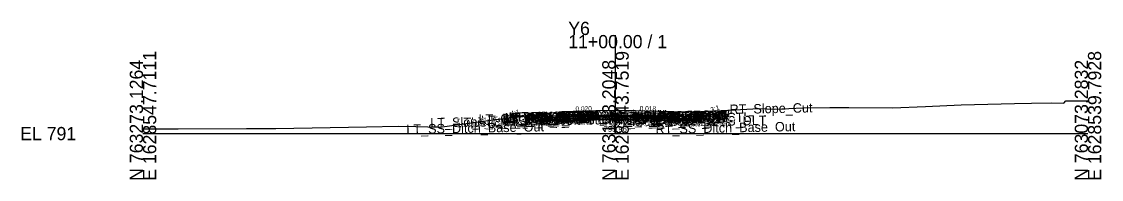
# Model space of a CAD drawing. Extents: x -26 to 203, y -10 to 6017.
# Drawn here: x -25.7 to 202.8, y 1990.3 to 2023.7 of the extents above; entities that cross this region are included whole.
import ezdxf

# ---------------------------------------------------------------- set-up
doc = ezdxf.new("R2010")
doc.units = 0
for name, color, linetype in [('Default', 7, 'Continuous'), ('Exist Cross Section Cell', 7, 'Continuous'), ('Exist XS Center Line Elevation Label', 7, 'Continuous'), ('Exist XS Ground Line', 7, 'Continuous'), ('Prop CMT Concrete Structures', 7, 'Continuous'), ('Prop CMT Pvmt Course 1', 7, 'Continuous'), ('Prop CMT Pvmt Course 2', 7, 'Continuous'), ('Prop CMT Pvmt Course 3', 7, 'Continuous'), ('Prop CMT Pvmt Surface', 7, 'Continuous'), ('Prop CMT Pvmt Surface Shoulder', 7, 'Continuous'), ('Prop CMT Pvmt Wedge Surface 2', 7, 'Continuous'), ('Prop CMT Pvmt Wedge Surface 3', 7, 'Continuous'), ('Prop CMT Shld Paved Course 1', 7, 'Continuous'), ('Prop CMT Shld Paved Course 2', 7, 'Continuous'), ('Prop CMT Shld Paved Course 3', 7, 'Continuous'), ('Prop CMT Slope Grass', 7, 'Continuous'), ('Prop CMT Subgrade Earthwork', 7, 'Continuous'), ('Prop XS SE Text', 7, 'Continuous'), ('Prop XS Side Slope Text', 7, 'Continuous'), ('Scratch_Level_0', 7, 'Continuous')]:
    doc.layers.add(name, color=color, linetype=linetype)

msp = doc.modelspace()

# ---------------------------------------------------------------- linework, layer by layer
at = {"layer": 'Exist Cross Section Cell'}
for p, q in [((100, 2000), (100, 2020.86)), ((0, 2000), (100, 2000)), ((100, 2000), (200, 2000))]:
    msp.add_line(p, q, dxfattribs=at)
at = {"layer": 'Exist XS Ground Line'}
msp.add_lwpolyline([(0, 2001.04), (7.45, 2001), (21.88, 2001.09), (28.09, 2001.08), (47.3, 2001.42), (53.98, 2001.55), (57.72, 2001.49), (62.83, 2001.34), (70.46, 2002.41), (77.39, 2003.33), (78.98, 2003.5), (88.61, 2004.67), (95.82, 2004.88), (100, 2004.96), (100.58, 2004.97), (108.96, 2004.77), (111.1, 2004.7), (112.32, 2004.65), (117.62, 2004.63), (119.45, 2004.75), (123.87, 2004.93), (130.4, 2005.31), (133.64, 2005.14), (139.71, 2005.44), (145.33, 2005.55), (149.38, 2005.51), (158.61, 2005.45), (165.59, 2005.76), (173.15, 2006.1), (184.44, 2006.35), (188.06, 2006.41), (192.31, 2006.52), (194.88, 2006.44), (195.3, 2006.94), (200, 2006.95)], dxfattribs=at)
at = {"layer": 'Prop CMT Concrete Structures'}
for points in [[(84.64, 2003.66), (84.64, 2003.08), (86.64, 2003.08)], [(86.64, 2003.66), (85.64, 2003.58), (84.64, 2003.66)], [(86.64, 2003.08), (86.64, 2003.66)], [(113.44, 2003.11), (113.44, 2003.69)], [(115.44, 2003.69), (115.44, 2003.11), (113.44, 2003.11)], [(113.44, 2003.69), (114.44, 2003.61), (115.44, 2003.69)]]:
    msp.add_lwpolyline(points, dxfattribs=at)
at = {"layer": 'Prop CMT Pvmt Course 1'}
for points in [[(100, 2003.93), (86.64, 2003.66)], [(86.64, 2003.41), (100, 2003.68)], [(86.64, 2003.66), (86.64, 2003.41)], [(100, 2003.93), (88.61, 2003.7)], [(100, 2003.8), (100, 2003.93)], [(100, 2003.68), (100, 2003.93)], [(100, 2003.93), (111.1, 2003.73)], [(100, 2003.8), (100, 2003.93)], [(100, 2003.93), (113.44, 2003.69)], [(100, 2003.68), (100, 2003.93)], [(113.44, 2003.44), (100, 2003.68)], [(113.44, 2003.69), (113.44, 2003.44)]]:
    msp.add_lwpolyline(points, dxfattribs=at)
at = {"layer": 'Prop CMT Pvmt Course 2'}
for points in [[(100, 2003.68), (86.64, 2003.41)], [(86.64, 2003.41), (86.64, 2003.08)], [(86.64, 2003.08), (100, 2003.34)], [(100, 2003.34), (100, 2003.68)], [(100, 2003.34), (100, 2003.68)], [(100, 2003.68), (113.44, 2003.44)], [(113.44, 2003.11), (100, 2003.34)], [(113.44, 2003.44), (113.44, 2003.11)]]:
    msp.add_lwpolyline(points, dxfattribs=at)
at = {"layer": 'Prop CMT Pvmt Course 3'}
msp.add_line((115.44, 2003.11), (115.94, 2003.11), dxfattribs=at)
for points in [[(100, 2003.34), (86.64, 2003.08)], [(86.64, 2003.08), (86.64, 2002.74)], [(86.64, 2002.74), (100, 2003.01)], [(100, 2003.01), (100, 2003.34)], [(100, 2003.34), (113.44, 2003.11)], [(100, 2003.01), (100, 2003.34)], [(113.44, 2002.77), (100, 2003.01)], [(113.44, 2003.11), (113.44, 2002.77)]]:
    msp.add_lwpolyline(points, dxfattribs=at)
at = {"layer": 'Prop CMT Pvmt Surface'}
for points in [[(100, 2003.93), (86.64, 2003.66)], [(100, 2003.93), (88.61, 2003.7)], [(100, 2003.93), (113.44, 2003.69)], [(100, 2003.93), (111.1, 2003.73)]]:
    msp.add_lwpolyline(points, dxfattribs=at)
at = {"layer": 'Prop CMT Pvmt Surface Shoulder'}
for points in [[(86.64, 2003.66), (86.64, 2003.66)], [(113.44, 2003.69), (113.44, 2003.69)]]:
    msp.add_lwpolyline(points, dxfattribs=at)
at = {"layer": 'Prop CMT Pvmt Wedge Surface 2'}
for points in [[(100, 2003.68), (88.61, 2003.45)], [(100, 2003.68), (100, 2003.93)], [(100, 2003.68), (100, 2003.93)], [(100, 2003.68), (100, 2003.93)], [(100, 2003.68), (100, 2003.93)], [(100, 2003.68), (111.1, 2003.48)]]:
    msp.add_lwpolyline(points, dxfattribs=at)
at = {"layer": 'Prop CMT Pvmt Wedge Surface 3'}
for points in [[(100, 2003.34), (88.61, 2003.11)], [(100, 2003.34), (100, 2003.93)], [(100, 2003.34), (100, 2003.93)], [(100, 2003.34), (100, 2003.93)], [(100, 2003.34), (100, 2003.93)], [(100, 2003.34), (111.1, 2003.15)]]:
    msp.add_lwpolyline(points, dxfattribs=at)
at = {"layer": 'Prop CMT Shld Paved Course 1'}
for points in [[(86.64, 2003.66), (86.64, 2003.66)], [(86.64, 2003.41), (86.64, 2003.66)], [(113.44, 2003.69), (113.44, 2003.69)], [(113.44, 2003.44), (113.44, 2003.69)]]:
    msp.add_lwpolyline(points, dxfattribs=at)
at = {"layer": 'Prop CMT Shld Paved Course 2'}
for p, q in [((84.64, 2003.08), (86.64, 2003.08)), ((115.44, 2003.11), (113.44, 2003.11))]:
    msp.add_line(p, q, dxfattribs=at)
for points in [[(86.64, 2003.08), (86.64, 2003.41)], [(113.44, 2003.11), (113.44, 2003.44)]]:
    msp.add_lwpolyline(points, dxfattribs=at)
at = {"layer": 'Prop CMT Shld Paved Course 3'}
for p, q in [((83.8, 2002.74), (86.64, 2002.74)), ((116.28, 2002.77), (113.44, 2002.77))]:
    msp.add_line(p, q, dxfattribs=at)
for points in [[(86.64, 2003.08), (84.64, 2003.08), (84.14, 2003.08), (83.8, 2002.74)], [(86.64, 2002.74), (86.64, 2003.08)], [(113.44, 2002.77), (113.44, 2003.11)], [(113.44, 2003.11), (115.94, 2003.11), (115.94, 2003.11), (116.28, 2002.77)]]:
    msp.add_lwpolyline(points, dxfattribs=at)
at = {"layer": 'Prop CMT Slope Grass'}
for points in [[(115.44, 2003.69), (120.44, 2003.79), (123.87, 2004.93)], [(84.64, 2003.66), (79.64, 2003.76), (78.35, 2003.43)]]:
    msp.add_lwpolyline(points, dxfattribs=at)
at = {"layer": 'Prop CMT Subgrade Earthwork'}
for p, q in [((83.8, 2002.74), (82.85, 2003.69)), ((86.64, 2002.74), (83.8, 2002.74)), ((113.44, 2002.77), (116.28, 2002.77)), ((116.28, 2002.77), (117.24, 2003.73))]:
    msp.add_line(p, q, dxfattribs=at)
for points in [[(100, 2003.01), (86.64, 2002.74)], [(100, 2003.01), (113.44, 2002.77)]]:
    msp.add_lwpolyline(points, dxfattribs=at)

# ---------------------------------------------------------------- texts
at = {"layer": 'Default'}
msp.add_text('-', height=0.0001, dxfattribs=at).set_placement((0, 2000))
at = {"layer": 'Exist Cross Section Cell'}
for s, p in [('Y6', (90, 2020.86)), ('11+00.00 / 1', (90, 2018.06)), ('EL 791', (-26, 1998.6))]:
    msp.add_text(s, height=2.8, dxfattribs=at).set_placement(p)
for s, p in [('E 1628547.7111', (2.8, 1990)), ('E 1628543.7519', (102.8, 1990)), ('E 1628539.7928', (202.8, 1990)), ('N 763273.1264', (0, 1990)), ('N 763173.2048', (100, 1990)), ('N 763073.2832', (200, 1990))]:
    msp.add_text(s, height=2.8, rotation=90, dxfattribs=at).set_placement(p)
at = {"layer": 'Exist XS Center Line Elevation Label'}
msp.add_text('795.96', height=1.2, dxfattribs=at).set_placement((97.5, 2000.36))
at = {"layer": 'Prop XS SE Text'}
for s, rotation, p in [('0.020', 1.1458, (91.55, 2004.76)), ('0.018', 358.9974, (105.12, 2004.84))]:
    msp.add_text(s, height=1, rotation=rotation, dxfattribs=at).set_placement(p)
at = {"layer": 'Prop XS Side Slope Text'}
for s, rotation, p in [('4:1', 14.0362, (77.94, 2003.72)), ('3:1', 18.4349, (120.29, 2004.53))]:
    msp.add_text(s, height=1, rotation=rotation, dxfattribs=at).set_placement(p)
at = {"layer": 'Scratch_Level_0'}
for s, p in [('LT_GS_OS_CTL', (71.04, 2002.05)), ('LT_PV2_OEEOP_W', (76.05, 2002.2)), ('LT_PV3_OEEOP_W', (76.05, 2001.86)), ('LT_PS3_OEOP', (76.31, 2001.87)), ('LT_PV1_OEEOP_W', (76.62, 2002.33)), ('LT_PS2_OEOP', (76.65, 2002.21)), ('LT_PV2_OEOT', (76.84, 2002.21)), ('LT_PV3_OEOT', (76.84, 2001.88)), ('LT_PV1_OEOT', (77.41, 2002.47)), ('LT_PS1_OEOP', (77.47, 2002.47)), ('LT_PV1_OEEOP', (78.51, 2002.5)), ('RT_PV1_PGL_W', (89.86, 2002.6)), ('LT_PV1_PGL_W', (89.91, 2002.6)), ('PV2_PGL', (93.93, 2002.55)), ('PV3_PGL', (93.93, 2002.22)), ('PV1_PGL', (94.49, 2002.82)), ('RT_PV2_OEEOP_W', (98.49, 2002.23)), ('RT_PV3_OEEOP_W', (98.49, 2001.9)), ('RT_PV1_OEEOP_W', (99.06, 2002.37)), ('RT_PS3_Shelf_Out', (100.5, 2001.8)), ('RT_PV1_OEEOP', (100.95, 2002.53)), ('RT_PV2_OEOT', (103.59, 2002.24)), ('RT_PV3_OEOT', (103.59, 2001.91)), ('RT_PS2_OEOP', (103.91, 2002.24)), ('RT_PV1_OEOT', (104.16, 2002.5)), ('RT_PS1_OEOP', (104.22, 2002.51)), ('RT_PS3_OEOP', (104.25, 2001.9)), ('RT_GS_OS_CTL', (107.79, 2002.08)), ('RT_Slope_Cut', (124.16, 2004.14)), ('LT_SS_Ditch_Base_Out', (55.75, 1999.9)), ('LT_Slope_Cut', (60.82, 2001.29)), ('LT_Sub_OSS_DLT', (66.39, 2001.34)), ('LT_Sub_Trench_Out', (69.44, 2001.4)), ('LT_PS3_Shelf_Out', (71.56, 2001.77)), ('LT_Sub_OEOT', (76.75, 2001.54)), ('Sub_PGL', (93.83, 2001.89)), ('RT_Sub_Trench_Out', (99.06, 2001.43)), ('RT_Sub_OEOT', (103.5, 2001.57)), ('RT_Sub_OSS_DLT', (108.5, 2001.37)), ('RT_SS_Ditch_Base_Out', (108.5, 1999.93))]:
    msp.add_text(s, height=2, rotation=1.1458, dxfattribs=at).set_placement(p)

doc.saveas('drawing.dxf')
